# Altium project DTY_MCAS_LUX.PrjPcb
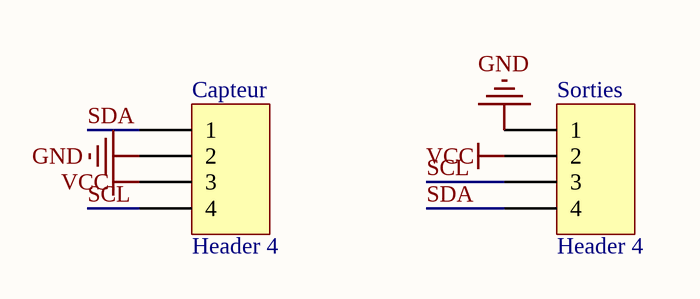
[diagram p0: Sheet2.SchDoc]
1 sheet, 2 parts. Net scope: global (net labels, ports and power ports of the same name join across sheets).
Board file: PCB2.PcbDoc

## Sheet Sheet2.SchDoc
size A4

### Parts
Capteur  Header 4  [LUXMETER]
Sorties  Header 4  [HDR1X4]

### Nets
GND: Capteur.2 Sorties.1
VCC: Capteur.3 Sorties.2
SCL: Capteur.4 Sorties.3
SDA: Capteur.1 Sorties.4

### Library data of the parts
Capteur Sorties = Header 4: Header, 4-Pin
